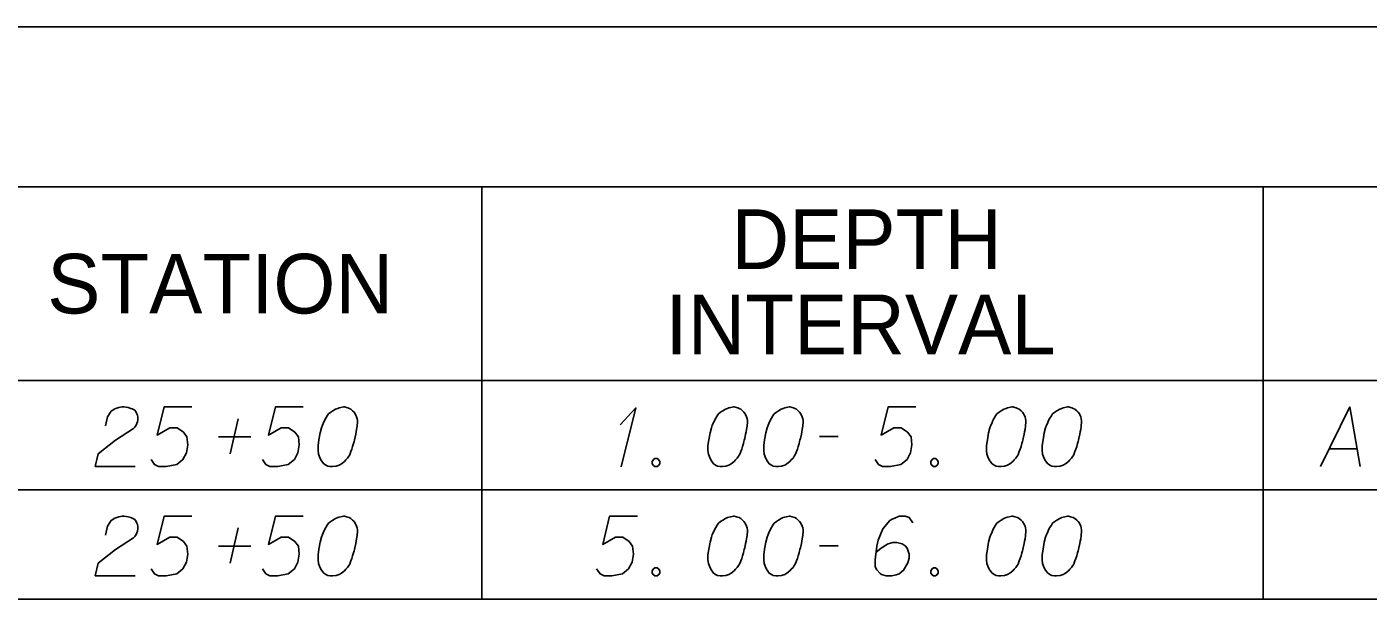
# Model space of a CAD drawing. Extents: x 2074207 to 2076812, y 516372 to 523312.
# Drawn here: x 2076345.6 to 2076453.5, y 516372.3 to 516418.4 of the extents above; entities that cross this region are included whole.
import ezdxf

# ---------------------------------------------------------------- set-up
doc = ezdxf.new("R2010")
doc.units = 0
for name, color, linetype in [('Prop DirtTable_ Soil Test Results - Outline (Major)', 7, 'Continuous'), ('Prop DirtTable_ Soil Test Results - Outline (Minor)', 7, 'Continuous'), ('Prop DirtTable_ Soil Test Results - Tx (Header - Small)', 7, 'Continuous'), ('Prop DirtTable_ Soil Test Results - Tx (Sample Data)', 7, 'Continuous')]:
    doc.layers.add(name, color=color, linetype=linetype)

msp = doc.modelspace()

# ---------------------------------------------------------------- linework, layer by layer
at = {"layer": 'Prop DirtTable_ Soil Test Results - Outline (Major)'}
for p, q in [((2076260.61, 516418.37), (2076811.9, 516418.37)), ((2076260.61, 516389.89), (2076811.9, 516389.89)), ((2076260.61, 516389.89), (2076811.9, 516389.89)), ((2076260.61, 516372.29), (2076811.9, 516372.29))]:
    msp.add_line(p, q, dxfattribs=at)
at = {"layer": 'Prop DirtTable_ Soil Test Results - Outline (Minor)'}
for p, q in [((2076260.61, 516405.49), (2076811.9, 516405.49)), ((2076382.2, 516405.49), (2076382.2, 516381.09)), ((2076445.06, 516405.49), (2076445.06, 516381.09)), ((2076260.61, 516381.09), (2076811.9, 516381.09)), ((2076260.61, 516381.09), (2076811.9, 516381.09)), ((2076382.2, 516381.09), (2076382.2, 516372.29)), ((2076445.06, 516381.09), (2076445.06, 516372.29)), ((2076260.61, 516372.29), (2076811.9, 516372.29))]:
    msp.add_line(p, q, dxfattribs=at)
at = {"layer": 'Prop DirtTable_ Soil Test Results - Tx (Sample Data)'}
for points in [[(2076351.93, 516386.25), (2076352.1, 516386.97), (2076352.39, 516387.43), (2076352.7, 516387.62), (2076353.02, 516387.73), (2076353.27, 516387.77), (2076353.44, 516387.77), (2076353.76, 516387.73), (2076353.97, 516387.65), (2076354.08, 516387.62), (2076354.29, 516387.5), (2076354.4, 516387.35), (2076354.47, 516387.2), (2076354.5, 516387.09), (2076354.54, 516386.94), (2076354.54, 516386.75), (2076354.5, 516386.56), (2076354.47, 516386.44), (2076354.4, 516386.29), (2076354.29, 516386.14), (2076354.18, 516386.03), (2076352.74, 516385.08), (2076351.36, 516383.99), (2076351.12, 516382.97), (2076354.33, 516382.97)], [(2076358.88, 516387.77), (2076356.65, 516387.77), (2076356.09, 516385.5), (2076357.11, 516386.07), (2076357.71, 516386.07), (2076358.21, 516385.73), (2076358.49, 516385.35), (2076358.56, 516384.71), (2076358.45, 516384.06), (2076358.17, 516383.53), (2076357.68, 516383.12), (2076356.83, 516382.97), (2076356.2, 516382.97), (2076355.88, 516383.12), (2076355.6, 516383.53)], [(2076367.84, 516387.77), (2076365.61, 516387.77), (2076365.05, 516385.5), (2076366.07, 516386.07), (2076366.67, 516386.07), (2076367.17, 516385.73), (2076367.45, 516385.35), (2076367.52, 516384.71), (2076367.41, 516384.06), (2076367.13, 516383.53), (2076366.64, 516383.12), (2076365.79, 516382.97), (2076365.16, 516382.97), (2076364.84, 516383.12), (2076364.56, 516383.53)], [(2076371.15, 516387.77), (2076371.08, 516387.77), (2076370.87, 516387.73), (2076370.73, 516387.69), (2076370.62, 516387.65), (2076370.45, 516387.58), (2076370.23, 516387.46), (2076370.06, 516387.35), (2076369.88, 516387.2), (2076369.78, 516387.05), (2076369.67, 516386.86), (2076369.56, 516386.67), (2076369.46, 516386.44), (2076369.39, 516386.29), (2076369.32, 516386.07), (2076369.21, 516385.69), (2076369.11, 516385.12), (2076369.04, 516384.67), (2076369.04, 516384.25), (2076369.07, 516383.95), (2076369.21, 516383.61), (2076369.32, 516383.42), (2076369.49, 516383.19), (2076369.71, 516383.04), (2076369.81, 516383), (2076370.02, 516382.97), (2076370.2, 516382.97), (2076370.48, 516383), (2076370.73, 516383.08), (2076370.91, 516383.19), (2076371.15, 516383.38), (2076371.26, 516383.5), (2076371.4, 516383.65), (2076371.5, 516383.8), (2076371.58, 516383.91), (2076371.65, 516384.1), (2076371.68, 516384.18), (2076371.75, 516384.37), (2076371.82, 516384.59), (2076371.89, 516384.82), (2076371.93, 516384.97), (2076371.96, 516385.08), (2076372, 516385.23), (2076372.07, 516385.57), (2076372.1, 516385.76), (2076372.14, 516385.95), (2076372.18, 516386.22), (2076372.21, 516386.56), (2076372.21, 516386.67), (2076372.18, 516386.82), (2076372.14, 516386.97), (2076372.03, 516387.2), (2076371.93, 516387.35), (2076371.82, 516387.46), (2076371.68, 516387.58), (2076371.54, 516387.65), (2076371.43, 516387.69), (2076371.33, 516387.73), (2076371.15, 516387.77)], [(2076393.34, 516386.33), (2076394.61, 516387.69), (2076393.41, 516382.93)], [(2076402.51, 516387.77), (2076402.44, 516387.77), (2076402.23, 516387.73), (2076402.09, 516387.69), (2076401.98, 516387.65), (2076401.81, 516387.58), (2076401.59, 516387.46), (2076401.42, 516387.35), (2076401.24, 516387.2), (2076401.14, 516387.05), (2076401.03, 516386.86), (2076400.92, 516386.67), (2076400.82, 516386.44), (2076400.75, 516386.29), (2076400.68, 516386.07), (2076400.57, 516385.69), (2076400.47, 516385.12), (2076400.4, 516384.67), (2076400.4, 516384.25), (2076400.43, 516383.95), (2076400.57, 516383.61), (2076400.68, 516383.42), (2076400.85, 516383.19), (2076401.07, 516383.04), (2076401.17, 516383), (2076401.38, 516382.97), (2076401.56, 516382.97), (2076401.84, 516383), (2076402.09, 516383.08), (2076402.27, 516383.19), (2076402.51, 516383.38), (2076402.62, 516383.5), (2076402.76, 516383.65), (2076402.86, 516383.8), (2076402.94, 516383.91), (2076403.01, 516384.1), (2076403.04, 516384.18), (2076403.11, 516384.37), (2076403.18, 516384.59), (2076403.25, 516384.82), (2076403.29, 516384.97), (2076403.32, 516385.08), (2076403.36, 516385.23), (2076403.43, 516385.57), (2076403.46, 516385.76), (2076403.5, 516385.95), (2076403.54, 516386.22), (2076403.57, 516386.56), (2076403.57, 516386.67), (2076403.54, 516386.82), (2076403.5, 516386.97), (2076403.39, 516387.2), (2076403.29, 516387.35), (2076403.18, 516387.46), (2076403.04, 516387.58), (2076402.9, 516387.65), (2076402.79, 516387.69), (2076402.69, 516387.73), (2076402.51, 516387.77)], [(2076406.99, 516387.77), (2076406.92, 516387.77), (2076406.71, 516387.73), (2076406.57, 516387.69), (2076406.46, 516387.65), (2076406.29, 516387.58), (2076406.07, 516387.46), (2076405.9, 516387.35), (2076405.72, 516387.2), (2076405.62, 516387.05), (2076405.51, 516386.86), (2076405.4, 516386.67), (2076405.3, 516386.44), (2076405.23, 516386.29), (2076405.16, 516386.07), (2076405.05, 516385.69), (2076404.95, 516385.12), (2076404.88, 516384.67), (2076404.88, 516384.25), (2076404.91, 516383.95), (2076405.05, 516383.61), (2076405.16, 516383.42), (2076405.33, 516383.19), (2076405.55, 516383.04), (2076405.65, 516383), (2076405.86, 516382.97), (2076406.04, 516382.97), (2076406.32, 516383), (2076406.57, 516383.08), (2076406.75, 516383.19), (2076406.99, 516383.38), (2076407.1, 516383.5), (2076407.24, 516383.65), (2076407.34, 516383.8), (2076407.42, 516383.91), (2076407.49, 516384.1), (2076407.52, 516384.18), (2076407.59, 516384.37), (2076407.66, 516384.59), (2076407.73, 516384.82), (2076407.77, 516384.97), (2076407.8, 516385.08), (2076407.84, 516385.23), (2076407.91, 516385.57), (2076407.94, 516385.76), (2076407.98, 516385.95), (2076408.02, 516386.22), (2076408.05, 516386.56), (2076408.05, 516386.67), (2076408.02, 516386.82), (2076407.98, 516386.97), (2076407.87, 516387.2), (2076407.77, 516387.35), (2076407.66, 516387.46), (2076407.52, 516387.58), (2076407.38, 516387.65), (2076407.27, 516387.69), (2076407.17, 516387.73), (2076406.99, 516387.77)], [(2076417.12, 516387.77), (2076414.89, 516387.77), (2076414.33, 516385.5), (2076415.35, 516386.07), (2076415.95, 516386.07), (2076416.45, 516385.73), (2076416.73, 516385.35), (2076416.8, 516384.71), (2076416.69, 516384.06), (2076416.41, 516383.53), (2076415.92, 516383.12), (2076415.07, 516382.97), (2076414.44, 516382.97), (2076414.12, 516383.12), (2076413.84, 516383.53)], [(2076424.91, 516387.77), (2076424.84, 516387.77), (2076424.63, 516387.73), (2076424.49, 516387.69), (2076424.38, 516387.65), (2076424.21, 516387.58), (2076423.99, 516387.46), (2076423.82, 516387.35), (2076423.64, 516387.2), (2076423.54, 516387.05), (2076423.43, 516386.86), (2076423.32, 516386.67), (2076423.22, 516386.44), (2076423.15, 516386.29), (2076423.08, 516386.07), (2076422.97, 516385.69), (2076422.87, 516385.12), (2076422.8, 516384.67), (2076422.8, 516384.25), (2076422.83, 516383.95), (2076422.97, 516383.61), (2076423.08, 516383.42), (2076423.25, 516383.19), (2076423.47, 516383.04), (2076423.57, 516383), (2076423.78, 516382.97), (2076423.96, 516382.97), (2076424.24, 516383), (2076424.49, 516383.08), (2076424.67, 516383.19), (2076424.91, 516383.38), (2076425.02, 516383.5), (2076425.16, 516383.65), (2076425.26, 516383.8), (2076425.34, 516383.91), (2076425.41, 516384.1), (2076425.44, 516384.18), (2076425.51, 516384.37), (2076425.58, 516384.59), (2076425.65, 516384.82), (2076425.69, 516384.97), (2076425.72, 516385.08), (2076425.76, 516385.23), (2076425.83, 516385.57), (2076425.86, 516385.76), (2076425.9, 516385.95), (2076425.94, 516386.22), (2076425.97, 516386.56), (2076425.97, 516386.67), (2076425.94, 516386.82), (2076425.9, 516386.97), (2076425.79, 516387.2), (2076425.69, 516387.35), (2076425.58, 516387.46), (2076425.44, 516387.58), (2076425.3, 516387.65), (2076425.19, 516387.69), (2076425.09, 516387.73), (2076424.91, 516387.77)], [(2076429.39, 516387.77), (2076429.32, 516387.77), (2076429.11, 516387.73), (2076428.97, 516387.69), (2076428.86, 516387.65), (2076428.69, 516387.58), (2076428.47, 516387.46), (2076428.3, 516387.35), (2076428.12, 516387.2), (2076428.02, 516387.05), (2076427.91, 516386.86), (2076427.8, 516386.67), (2076427.7, 516386.44), (2076427.63, 516386.29), (2076427.56, 516386.07), (2076427.45, 516385.69), (2076427.35, 516385.12), (2076427.28, 516384.67), (2076427.28, 516384.25), (2076427.31, 516383.95), (2076427.45, 516383.61), (2076427.56, 516383.42), (2076427.73, 516383.19), (2076427.95, 516383.04), (2076428.05, 516383), (2076428.26, 516382.97), (2076428.44, 516382.97), (2076428.72, 516383), (2076428.97, 516383.08), (2076429.15, 516383.19), (2076429.39, 516383.38), (2076429.5, 516383.5), (2076429.64, 516383.65), (2076429.74, 516383.8), (2076429.82, 516383.91), (2076429.89, 516384.1), (2076429.92, 516384.18), (2076429.99, 516384.37), (2076430.06, 516384.59), (2076430.13, 516384.82), (2076430.17, 516384.97), (2076430.2, 516385.08), (2076430.24, 516385.23), (2076430.31, 516385.57), (2076430.34, 516385.76), (2076430.38, 516385.95), (2076430.42, 516386.22), (2076430.45, 516386.56), (2076430.45, 516386.67), (2076430.42, 516386.82), (2076430.38, 516386.97), (2076430.27, 516387.2), (2076430.17, 516387.35), (2076430.06, 516387.46), (2076429.92, 516387.58), (2076429.78, 516387.65), (2076429.67, 516387.69), (2076429.57, 516387.73), (2076429.39, 516387.77)], [(2076449.68, 516382.97), (2076452.04, 516387.77), (2076452.85, 516382.97)], [(2076361.98, 516383.99), (2076362.62, 516386.82)], [(2076361.03, 516385.35), (2076363.64, 516385.35)], [(2076409.36, 516385.39), (2076410.87, 516385.39)], [(2076450.38, 516384.4), (2076452.6, 516384.4)], [(2076396.13, 516383.61), (2076396.3, 516383.61), (2076396.41, 516383.53), (2076396.52, 516383.38), (2076396.52, 516383.19), (2076396.41, 516383.04), (2076396.3, 516382.97), (2076396.13, 516382.97), (2076396.02, 516383.04), (2076395.92, 516383.19), (2076395.92, 516383.38), (2076396.02, 516383.53), (2076396.13, 516383.61)], [(2076418.53, 516383.61), (2076418.7, 516383.61), (2076418.81, 516383.53), (2076418.92, 516383.38), (2076418.92, 516383.19), (2076418.81, 516383.04), (2076418.7, 516382.97), (2076418.53, 516382.97), (2076418.42, 516383.04), (2076418.32, 516383.19), (2076418.32, 516383.38), (2076418.42, 516383.53), (2076418.53, 516383.61)], [(2076351.93, 516377.45), (2076352.1, 516378.17), (2076352.39, 516378.63), (2076352.7, 516378.82), (2076353.02, 516378.93), (2076353.27, 516378.97), (2076353.44, 516378.97), (2076353.76, 516378.93), (2076353.97, 516378.85), (2076354.08, 516378.82), (2076354.29, 516378.7), (2076354.4, 516378.55), (2076354.47, 516378.4), (2076354.5, 516378.29), (2076354.54, 516378.14), (2076354.54, 516377.95), (2076354.5, 516377.76), (2076354.47, 516377.64), (2076354.4, 516377.49), (2076354.29, 516377.34), (2076354.18, 516377.23), (2076352.74, 516376.28), (2076351.36, 516375.19), (2076351.12, 516374.17), (2076354.33, 516374.17)], [(2076358.88, 516378.97), (2076356.65, 516378.97), (2076356.09, 516376.7), (2076357.11, 516377.27), (2076357.71, 516377.27), (2076358.21, 516376.93), (2076358.49, 516376.55), (2076358.56, 516375.91), (2076358.45, 516375.26), (2076358.17, 516374.73), (2076357.68, 516374.32), (2076356.83, 516374.17), (2076356.2, 516374.17), (2076355.88, 516374.32), (2076355.6, 516374.73)], [(2076367.84, 516378.97), (2076365.61, 516378.97), (2076365.05, 516376.7), (2076366.07, 516377.27), (2076366.67, 516377.27), (2076367.17, 516376.93), (2076367.45, 516376.55), (2076367.52, 516375.91), (2076367.41, 516375.26), (2076367.13, 516374.73), (2076366.64, 516374.32), (2076365.79, 516374.17), (2076365.16, 516374.17), (2076364.84, 516374.32), (2076364.56, 516374.73)], [(2076371.15, 516378.97), (2076371.08, 516378.97), (2076370.87, 516378.93), (2076370.73, 516378.89), (2076370.62, 516378.85), (2076370.45, 516378.78), (2076370.23, 516378.66), (2076370.06, 516378.55), (2076369.88, 516378.4), (2076369.78, 516378.25), (2076369.67, 516378.06), (2076369.56, 516377.87), (2076369.46, 516377.64), (2076369.39, 516377.49), (2076369.32, 516377.27), (2076369.21, 516376.89), (2076369.11, 516376.32), (2076369.04, 516375.87), (2076369.04, 516375.45), (2076369.07, 516375.15), (2076369.21, 516374.81), (2076369.32, 516374.62), (2076369.49, 516374.39), (2076369.71, 516374.24), (2076369.81, 516374.2), (2076370.02, 516374.17), (2076370.2, 516374.17), (2076370.48, 516374.2), (2076370.73, 516374.28), (2076370.91, 516374.39), (2076371.15, 516374.58), (2076371.26, 516374.7), (2076371.4, 516374.85), (2076371.5, 516375), (2076371.58, 516375.11), (2076371.65, 516375.3), (2076371.68, 516375.38), (2076371.75, 516375.57), (2076371.82, 516375.79), (2076371.89, 516376.02), (2076371.93, 516376.17), (2076371.96, 516376.28), (2076372, 516376.43), (2076372.07, 516376.77), (2076372.1, 516376.96), (2076372.14, 516377.15), (2076372.18, 516377.42), (2076372.21, 516377.76), (2076372.21, 516377.87), (2076372.18, 516378.02), (2076372.14, 516378.17), (2076372.03, 516378.4), (2076371.93, 516378.55), (2076371.82, 516378.66), (2076371.68, 516378.78), (2076371.54, 516378.85), (2076371.43, 516378.89), (2076371.33, 516378.93), (2076371.15, 516378.97)], [(2076394.72, 516378.97), (2076392.49, 516378.97), (2076391.93, 516376.7), (2076392.95, 516377.27), (2076393.55, 516377.27), (2076394.05, 516376.93), (2076394.33, 516376.55), (2076394.4, 516375.91), (2076394.29, 516375.26), (2076394.01, 516374.73), (2076393.52, 516374.32), (2076392.67, 516374.17), (2076392.04, 516374.17), (2076391.72, 516374.32), (2076391.44, 516374.73)], [(2076402.51, 516378.97), (2076402.44, 516378.97), (2076402.23, 516378.93), (2076402.09, 516378.89), (2076401.98, 516378.85), (2076401.81, 516378.78), (2076401.59, 516378.66), (2076401.42, 516378.55), (2076401.24, 516378.4), (2076401.14, 516378.25), (2076401.03, 516378.06), (2076400.92, 516377.87), (2076400.82, 516377.64), (2076400.75, 516377.49), (2076400.68, 516377.27), (2076400.57, 516376.89), (2076400.47, 516376.32), (2076400.4, 516375.87), (2076400.4, 516375.45), (2076400.43, 516375.15), (2076400.57, 516374.81), (2076400.68, 516374.62), (2076400.85, 516374.39), (2076401.07, 516374.24), (2076401.17, 516374.2), (2076401.38, 516374.17), (2076401.56, 516374.17), (2076401.84, 516374.2), (2076402.09, 516374.28), (2076402.27, 516374.39), (2076402.51, 516374.58), (2076402.62, 516374.7), (2076402.76, 516374.85), (2076402.86, 516375), (2076402.94, 516375.11), (2076403.01, 516375.3), (2076403.04, 516375.38), (2076403.11, 516375.57), (2076403.18, 516375.79), (2076403.25, 516376.02), (2076403.29, 516376.17), (2076403.32, 516376.28), (2076403.36, 516376.43), (2076403.43, 516376.77), (2076403.46, 516376.96), (2076403.5, 516377.15), (2076403.54, 516377.42), (2076403.57, 516377.76), (2076403.57, 516377.87), (2076403.54, 516378.02), (2076403.5, 516378.17), (2076403.39, 516378.4), (2076403.29, 516378.55), (2076403.18, 516378.66), (2076403.04, 516378.78), (2076402.9, 516378.85), (2076402.79, 516378.89), (2076402.69, 516378.93), (2076402.51, 516378.97)], [(2076406.99, 516378.97), (2076406.92, 516378.97), (2076406.71, 516378.93), (2076406.57, 516378.89), (2076406.46, 516378.85), (2076406.29, 516378.78), (2076406.07, 516378.66), (2076405.9, 516378.55), (2076405.72, 516378.4), (2076405.62, 516378.25), (2076405.51, 516378.06), (2076405.4, 516377.87), (2076405.3, 516377.64), (2076405.23, 516377.49), (2076405.16, 516377.27), (2076405.05, 516376.89), (2076404.95, 516376.32), (2076404.88, 516375.87), (2076404.88, 516375.45), (2076404.91, 516375.15), (2076405.05, 516374.81), (2076405.16, 516374.62), (2076405.33, 516374.39), (2076405.55, 516374.24), (2076405.65, 516374.2), (2076405.86, 516374.17), (2076406.04, 516374.17), (2076406.32, 516374.2), (2076406.57, 516374.28), (2076406.75, 516374.39), (2076406.99, 516374.58), (2076407.1, 516374.7), (2076407.24, 516374.85), (2076407.34, 516375), (2076407.42, 516375.11), (2076407.49, 516375.3), (2076407.52, 516375.38), (2076407.59, 516375.57), (2076407.66, 516375.79), (2076407.73, 516376.02), (2076407.77, 516376.17), (2076407.8, 516376.28), (2076407.84, 516376.43), (2076407.91, 516376.77), (2076407.94, 516376.96), (2076407.98, 516377.15), (2076408.02, 516377.42), (2076408.05, 516377.76), (2076408.05, 516377.87), (2076408.02, 516378.02), (2076407.98, 516378.17), (2076407.87, 516378.4), (2076407.77, 516378.55), (2076407.66, 516378.66), (2076407.52, 516378.78), (2076407.38, 516378.85), (2076407.27, 516378.89), (2076407.17, 516378.93), (2076406.99, 516378.97)], [(2076416.87, 516378.44), (2076416.59, 516378.85), (2076416.27, 516378.97), (2076415.78, 516378.97), (2076415.42, 516378.82), (2076415.21, 516378.74), (2076415.03, 516378.63), (2076414.47, 516377.95), (2076414.08, 516377.04), (2076413.98, 516376.55), (2076413.84, 516375.45), (2076413.84, 516374.88), (2076413.98, 516374.66), (2076414.26, 516374.36), (2076414.36, 516374.28), (2076414.72, 516374.17), (2076415.18, 516374.17), (2076415.53, 516374.24), (2076415.78, 516374.32), (2076416.13, 516374.62), (2076416.48, 516375.22), (2076416.59, 516375.6), (2076416.59, 516375.91), (2076416.41, 516376.4), (2076416.27, 516376.59), (2076416.02, 516376.74), (2076415.6, 516376.85), (2076415.28, 516376.85), (2076414.89, 516376.74), (2076414.65, 516376.62), (2076414.22, 516376.32), (2076414.01, 516376.13), (2076413.91, 516376.02)], [(2076424.91, 516378.97), (2076424.84, 516378.97), (2076424.63, 516378.93), (2076424.49, 516378.89), (2076424.38, 516378.85), (2076424.21, 516378.78), (2076423.99, 516378.66), (2076423.82, 516378.55), (2076423.64, 516378.4), (2076423.54, 516378.25), (2076423.43, 516378.06), (2076423.32, 516377.87), (2076423.22, 516377.64), (2076423.15, 516377.49), (2076423.08, 516377.27), (2076422.97, 516376.89), (2076422.87, 516376.32), (2076422.8, 516375.87), (2076422.8, 516375.45), (2076422.83, 516375.15), (2076422.97, 516374.81), (2076423.08, 516374.62), (2076423.25, 516374.39), (2076423.47, 516374.24), (2076423.57, 516374.2), (2076423.78, 516374.17), (2076423.96, 516374.17), (2076424.24, 516374.2), (2076424.49, 516374.28), (2076424.67, 516374.39), (2076424.91, 516374.58), (2076425.02, 516374.7), (2076425.16, 516374.85), (2076425.26, 516375), (2076425.34, 516375.11), (2076425.41, 516375.3), (2076425.44, 516375.38), (2076425.51, 516375.57), (2076425.58, 516375.79), (2076425.65, 516376.02), (2076425.69, 516376.17), (2076425.72, 516376.28), (2076425.76, 516376.43), (2076425.83, 516376.77), (2076425.86, 516376.96), (2076425.9, 516377.15), (2076425.94, 516377.42), (2076425.97, 516377.76), (2076425.97, 516377.87), (2076425.94, 516378.02), (2076425.9, 516378.17), (2076425.79, 516378.4), (2076425.69, 516378.55), (2076425.58, 516378.66), (2076425.44, 516378.78), (2076425.3, 516378.85), (2076425.19, 516378.89), (2076425.09, 516378.93), (2076424.91, 516378.97)], [(2076429.39, 516378.97), (2076429.32, 516378.97), (2076429.11, 516378.93), (2076428.97, 516378.89), (2076428.86, 516378.85), (2076428.69, 516378.78), (2076428.47, 516378.66), (2076428.3, 516378.55), (2076428.12, 516378.4), (2076428.02, 516378.25), (2076427.91, 516378.06), (2076427.8, 516377.87), (2076427.7, 516377.64), (2076427.63, 516377.49), (2076427.56, 516377.27), (2076427.45, 516376.89), (2076427.35, 516376.32), (2076427.28, 516375.87), (2076427.28, 516375.45), (2076427.31, 516375.15), (2076427.45, 516374.81), (2076427.56, 516374.62), (2076427.73, 516374.39), (2076427.95, 516374.24), (2076428.05, 516374.2), (2076428.26, 516374.17), (2076428.44, 516374.17), (2076428.72, 516374.2), (2076428.97, 516374.28), (2076429.15, 516374.39), (2076429.39, 516374.58), (2076429.5, 516374.7), (2076429.64, 516374.85), (2076429.74, 516375), (2076429.82, 516375.11), (2076429.89, 516375.3), (2076429.92, 516375.38), (2076429.99, 516375.57), (2076430.06, 516375.79), (2076430.13, 516376.02), (2076430.17, 516376.17), (2076430.2, 516376.28), (2076430.24, 516376.43), (2076430.31, 516376.77), (2076430.34, 516376.96), (2076430.38, 516377.15), (2076430.42, 516377.42), (2076430.45, 516377.76), (2076430.45, 516377.87), (2076430.42, 516378.02), (2076430.38, 516378.17), (2076430.27, 516378.4), (2076430.17, 516378.55), (2076430.06, 516378.66), (2076429.92, 516378.78), (2076429.78, 516378.85), (2076429.67, 516378.89), (2076429.57, 516378.93), (2076429.39, 516378.97)], [(2076361.98, 516375.19), (2076362.62, 516378.02)], [(2076361.03, 516376.55), (2076363.64, 516376.55)], [(2076409.36, 516376.59), (2076410.87, 516376.59)], [(2076396.13, 516374.81), (2076396.3, 516374.81), (2076396.41, 516374.73), (2076396.52, 516374.58), (2076396.52, 516374.39), (2076396.41, 516374.24), (2076396.3, 516374.17), (2076396.13, 516374.17), (2076396.02, 516374.24), (2076395.92, 516374.39), (2076395.92, 516374.58), (2076396.02, 516374.73), (2076396.13, 516374.81)], [(2076418.53, 516374.81), (2076418.7, 516374.81), (2076418.81, 516374.73), (2076418.92, 516374.58), (2076418.92, 516374.39), (2076418.81, 516374.24), (2076418.7, 516374.17), (2076418.53, 516374.17), (2076418.42, 516374.24), (2076418.32, 516374.39), (2076418.32, 516374.58), (2076418.42, 516374.73), (2076418.53, 516374.81)]]:
    msp.add_lwpolyline(points, dxfattribs=at)

# ---------------------------------------------------------------- texts
at = {"layer": 'Prop DirtTable_ Soil Test Results - Tx (Header - Small)'}
for s, p in [('DEPTH', (2076402.29, 516398.87)), ('STATION', (2076347.25, 516395.29)), ('INTERVAL', (2076396.98, 516392.01))]:
    msp.add_text(s, height=4.8, dxfattribs=at).set_placement(p)

doc.saveas('drawing.dxf')
